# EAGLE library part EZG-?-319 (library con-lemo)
LEMO Connector Source: http://www.lemo.com/pdfs/catalog/ROW/German/unipole_multipole.pdf
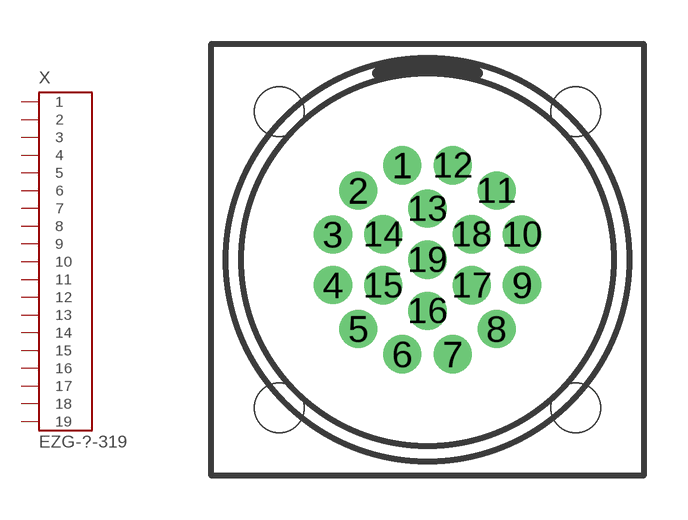
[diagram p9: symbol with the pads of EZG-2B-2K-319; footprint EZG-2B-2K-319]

Designator prefix X

## EZG-2B-319 (OC_FARNELL: unknown; OC_NEWARK: unknown)  [EZG-2B-2K-319]
1  1  pas
2  2  pas
3  3  pas
4  4  pas
5  5  pas
6  6  pas
7  7  pas
8  8  pas
9  9  pas
10  10  pas
11  11  pas
12  12  pas
13  13  pas
14  14  pas
15  15  pas
16  16  pas
17  17  pas
18  18  pas
19  19  pas

## EZG-2K-319 (OC_FARNELL: unknown; OC_NEWARK: unknown)  [EZG-2B-2K-319]
Pads as for EZG-2B-2K-319

## Footprint EZG-2B-2K-319 (pad centres in mm)
LEMO Connector Source: http://www.lemo.com/pdfs/catalog/ROW/German/unipole_multipole.pdf
drill 0.8 pad 1.3 round: 1 -0.867,3.236; 2 -2.369,2.369; 3 -3.236,0.867; 4 -3.236,-0.867; 5 -2.369,-2.369; 6 -0.867,-3.236; 7 0.867,-3.236; 8 2.369,-2.369; 9 3.236,-0.867; 10 3.236,0.867; 11 2.369,2.369; 12 0.867,3.236; 13 0,1.75; 14 -1.516,0.875; 15 -1.516,-0.875; 16 0,-1.75; 17 1.516,-0.875; 18 1.516,0.875; 19 0,0
hole 1.7 at -5.08,5.08
hole 1.7 at 5.08,5.08
hole 1.7 at 5.08,-5.08
hole 1.7 at -5.08,-5.08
